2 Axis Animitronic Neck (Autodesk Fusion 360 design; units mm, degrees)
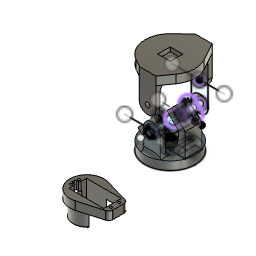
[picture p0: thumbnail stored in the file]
sketch "Sketch1" plane through (0, 0, 0) normal (0, 0, 1) x axis (1, 0, 0)
  line L1 (-39.2157, 5) -> (0, 5)
  line L2 (-39.2157, -5) -> (0, -5)
  line L3 (-14.1421, 5) -> (-14.1421, -5)
  line L4 (33.8579, 5) -> (33.8579, -5)
  line L5 (30.8579, -10.5) -> (0, -10.5)
  line L6 (30.8579, 10.5) -> (0, 10.5)
  line L7 (33.8579, 0) -> (-14.1421, 0)
  line L8 (30.8579, -10.5) -> (30.8579, 0)
  line L9 (30.8579, 10.5) -> (30.8579, 0)
  line L10 (-11.1421, 10.5) -> (-11.1421, 0)
  line L11 (-11.1421, -10.5) -> (-11.1421, 0)
  line L12 (37.8579, 10.5) -> (37.8579, 0)
  line L13 (37.8579, -10.5) -> (37.8579, 0)
  line L14 (5.6339, 19.7106) -> (37.8579, 10.5)
  line L15 (5.6339, -19.7106) -> (37.8579, -10.5)
  line L16 (-11.1421, 10.5) -> (0, 10.5)
  line L17 (-11.1421, -10.5) -> (0, -10.5)
  circle C1 centre (0, 0) radius 15
  circle C2 centre (-14.1421, -5) radius 1.5
  circle C3 centre (-14.1421, 5) radius 1.5
  circle C4 centre (33.8579, 5) radius 1.5
  circle C5 centre (33.8579, -5) radius 1.5
  arc A1 centre (0, 0) radius 20.5 clockwise from (5.6339, -19.7106) to (5.6339, 19.7106)
  arc A2 centre (0, 0) radius 16.625 clockwise from (12.8896, -10.5) to (12.8896, 10.5)
  point P1 (0, 0)
  point P2 (0, 0)
  point P8 (-14.1421, -5)
  point P9 (-14.1421, 5)
  point P10 (-14.1421, -5)
  point P11 (-14.1421, 5)
  point P13 (33.8579, 5)
  point P14 (33.8579, 5)
  point P12 (33.8579, -5)
  point P15 (33.8579, -5)
  point P18 (-14.1421, 0)
  point P19 (33.8579, 0)
  point P32 (12.8896, 10.5)
  point P33 (12.8896, -10.5)
  coincident P1 P2
  coincident C1 P8
  coincident L2 P8
  coincident C1 P9
  coincident L1 P9
  coincident P8 P10
  coincident P9 P11
  coincident P13 P14
  coincident P12 P15
  midpoint L3 P18
  midpoint L4 P19
  perpendicular L4 L7
  coincident L6 P32
  coincident L5 P33
  dimension "d1" diameter A2 = 33.25
  dimension "d3" diameter C1 = 30
  dimension "d6" diameter C2 = 3
  dimension "d7" diameter C3 = 3
  dimension "d8" = 48
  dimension "d9" diameter C4 = 3
  dimension "d10" diameter C5 = 3
extrude "Extrude1" new body sketch "Sketch1" profile of A2 A1 C2 C3 C4 C5 L17 L5 L16 L6 L9 L8 L11 L10 L13 L12 L14 L15 along normal blind 10
extrude "Extrude2" add sketch "Sketch1" profile of A2 C2 C3 L17 L5 L16 L6 L11 L10 against normal blind 20
sketch "Sketch2" plane through (0, 0, -20) normal (0, 0, -1) x axis (1, 0, 0)
  line L1 (-11.1421, -10.5) -> (12.8896, -10.5)
  line L2 (-11.1421, 10.5) -> (-11.1421, -10.5)
  line L3 (12.8896, 10.5) -> (-11.1421, 10.5)
  line L4 (-19.0195, 0) -> (-11.1421, 0)
  line L5 (-19.0195, -5) -> (-19.0195, 0)
  line L6 (-11.1421, -5) -> (-19.0195, -5)
  line L7 (-19.0195, 5) -> (-19.0195, 0)
  line L8 (-11.1421, 5) -> (-19.0195, 5)
  circle C1 centre (-14.1421, 5) radius 1.5
  circle C2 centre (-14.1421, -5) radius 1.5
  arc A1 centre (0, 0) radius 16.625 clockwise from (12.8896, -10.5) to (12.8896, 10.5)
  point P9 (-11.1421, 0)
  point P12 (-11.1421, -5)
  point P14 (-11.1421, 5)
  point P10 (-19.0195, 0)
  point P11 (-19.0195, -5)
  point P13 (-19.0195, 5)
  midpoint L2 P9
  perpendicular L2 L4
  perpendicular L4 L5
  coincident L2 P12
  perpendicular L2 L6
  perpendicular L4 L7
  coincident L2 P14
  perpendicular L2 L8
  dimension "d20" distance P10 P11 = 5
  dimension "d21" distance P10 P13 = 5
extrude "Extrude3" add sketch "Sketch1" profile of C2 C3 against normal blind 20
extrude "Extrude4" cut sketch "Sketch2" profile of C1 C2 L2 A1 L4 L6 L8 against normal blind 20
sketch "Sketch3" plane through (0, 0, 10) normal (0, 0, 1) x axis (-1, 0, 0)
  line L1 (-30.8579, 10.5) -> (-30.8579, -10.5)
  line L2 (11.1421, 10.5) -> (-30.8579, 10.5)
  line L3 (11.1421, -10.5) -> (11.1421, 10.5)
  line L4 (-30.8579, -10.5) -> (11.1421, -10.5)
  line L5 (-37.8579, -10.5) -> (-37.8579, 10.5)
  line L6 (-5.6339, -19.7106) -> (-37.8579, -10.5)
  line L7 (-37.8579, 10.5) -> (-5.6339, 19.7106)
  line L8 (16.1421, 0) -> (11.1421, 0)
  line L9 (16.1421, -2.5) -> (16.1421, 0)
  line L10 (11.1421, -2.5) -> (16.1421, -2.5)
  line L11 (16.1421, 2.5) -> (16.1421, 0)
  line L12 (11.1421, 2.5) -> (16.1421, 2.5)
  circle C1 centre (14.1421, -5) radius 1.5
  circle C2 centre (14.1421, 5) radius 1.5
  circle C3 centre (-33.8579, -5) radius 1.5
  circle C4 centre (-33.8579, 5) radius 1.5
  arc A1 centre (0, 0) radius 20.5 clockwise from (-5.6339, 19.7106) to (-5.6339, -19.7106)
  point P15 (11.1421, 0)
  point P18 (11.1421, -2.5)
  point P20 (11.1421, 2.5)
  point P16 (16.1421, 0)
  point P17 (16.1421, -2.5)
  point P19 (16.1421, 2.5)
  midpoint L3 P15
  perpendicular L3 L8
  perpendicular L8 L9
  coincident L3 P18
  perpendicular L3 L10
  perpendicular L8 L11
  coincident L3 P20
  perpendicular L3 L12
  dimension "d26" distance P15 P16 = 5
  dimension "d27" distance P16 P17 = 2.5
  dimension "d28" distance P16 P19 = 2.5
extrude "Extrude5" cut sketch "Sketch3" profile of L3 L8 L9 L10 L11 L12 against normal blind 21
fillet "Fillet1" radius 1.5
fillet "Fillet2" radius 1.5
fillet "Fillet3" radius 5
fillet "Fillet4" radius 2
move "Move1"
sketch "Sketch1" plane through (0, 0, 0) normal (0, 0, 1) x axis (1, 0, 0)
  line L1 (0, 24) -> (0, 0)
  line L2 (4, 24) -> (4, 12.2838)
  line L3 (-4, 24) -> (-4, 12.2838)
  circle C1 centre (0, 0) radius 30
  arc A1 centre (0, 24) radius 4 clockwise from (-4, 24) to (4, 24)
  arc A2 centre (0, 0) radius 7.625 clockwise from (6.4033, 4.1398) to (-6.4033, 4.1398)
  circle C2 centre (0, 24) radius 1.5
  arc A3 centre (-19, 12.2838) radius 15 clockwise from (-4, 12.2838) to (-6.4033, 4.1398)
  arc A4 centre (19, 12.2838) radius 15 clockwise from (6.4033, 4.1398) to (4, 12.2838)
  point P1 (0, 0)
  point P2 (0, 0)
  point P4 (0, 0)
  point P5 (0, 24)
  point P6 (0, 24)
  coincident P1 P2
  concentric C1 A2
  coincident P2 P4
  vertical L1
  coincident P5 P6
  concentric A1 C2
  tangent L3 A3
  tangent A2 A3
  tangent L2 A4
  tangent A2 A4
  dimension "d39" diameter C1 = 60
  dimension "d40" diameter A2 = 15.25
  dimension "d41" distance P4 P5 = 24
  dimension "d42" diameter A1 = 8
  dimension "d45" diameter C2 = 3
  dimension "d46" radius A3 = 15
  dimension "d47" radius A4 = 15
extrude "Extrude1" new body sketch "Sketch1" profile of C1 A2 A1 L2 L3 C2 A3 A4 along normal blind 10
extrude "Extrude2" cut sketch "Sketch1" profile of A2 A1 L2 L3 C2 A3 A4 along normal blind 7
sketch "Sketch2" plane through (0, 0, 10) normal (0, 0, 1) x axis (-1, 0, 0)
  line L1 (54.6614, 0) -> (0, 0)
  line L2 (-20, 0) -> (0, 0)
  line L3 (-20, 10) -> (-20, 0)
  line L4 (-28, 10) -> (-20, 10)
  line L5 (-28, -10) -> (-28, 10)
  line L6 (-20, -10) -> (-28, -10)
  line L7 (-20, 0) -> (-20, -10)
  circle C1 centre (0, 0) radius 30
  point P2 (0, 0)
  point P3 (0, 0)
  point P5 (-20, 0)
  point P6 (-20, 10)
  point P7 (-28, 10)
  point P8 (-28, -10)
  coincident P2 P3
  horizontal L1
  parallel L1 L2
  perpendicular L1 L3
  perpendicular L3 L4
  perpendicular L1 L5
  perpendicular L5 L6
  perpendicular L2 L7
  dimension "d52" distance P3 P5 = 20
  dimension "d53" distance P5 P6 = 10
  dimension "d54" distance P6 P7 = 8
  dimension "d55" distance P7 P8 = 20
extrude "Extrude3" add sketch "Sketch2" profile of L3 L4 L5 L6 L7 along normal blind 25
sketch "Sketch3" plane through (0, 10, 0) normal (0, 1, 0) x axis (-1, 0, 0)
  line L1 (-20, 10) -> (-28, 10)
  line L2 (-20, 35) -> (-20, 10)
  line L3 (-28, 35) -> (-20, 35)
  line L4 (-28, 10) -> (-28, 35)
  line L5 (-5.8579, 49.1421) -> (-20, 35)
  line L6 (25, 35) -> (-20, 35)
  line L7 (-11.5147, 54.799) -> (-28, 38.3137)
  line L8 (-28, 38.3137) -> (-28, 35)
  line L9 (-25.6569, 40.6569) -> (-20, 35)
  line L10 (-11.5147, 54.799) -> (-5.8579, 49.1421)
  point P4 (-20, 35)
  point P6 (-20, 35)
  point P5 (-28, 35)
  point P8 (-28, 35)
  point P10 (-20, 35)
  point P11 (-25.6569, 40.6569)
  horizontal L6
  coincident P4 P6
  coincident P5 P8
  perpendicular L3 L8
  coincident P4 P10
  perpendicular L7 L9
  coincident L7 P11
  dimension "d59" angle L5 L6 = 45
  dimension "d61" = 20
extrude "Extrude4" add sketch "Sketch3" profile of L3 L5 L8 L7 L9 L10 against normal blind 20
sketch "Sketch4" plane through (0, 10, 0) normal (0, 1, 0) x axis (-1, 0, 0)
  line L1 (-20, 10) -> (-28, 10)
  line L2 (-20, 35) -> (-20, 10)
  line L3 (-5.8579, 49.1421) -> (-20, 35)
  line L4 (-11.5147, 54.799) -> (-5.8579, 49.1421)
  line L5 (-28, 38.3137) -> (-11.5147, 54.799)
  line L6 (-28, 10) -> (-28, 38.3137)
  line L7 (-11.5147, 49.1421) -> (-8.6863, 51.9706)
  line L8 (-18.5858, 42.0711) -> (-11.5147, 49.1421)
  line L9 (23.1335, 14.4939) -> (-11.5147, 49.1421)
  line L10 (16.0624, 7.4228) -> (-18.5858, 42.0711)
  line L11 (21.4524, -6.4524) -> (-20, 35)
  line L12 (-5.8579, 49.1421) -> (-20, 35)
  line L13 (23.1335, 20.1508) -> (8.9914, 6.0086)
  line L14 (14.6482, 0.3518) -> (8.9914, 6.0086)
  line L15 (28.1635, 13.867) -> (14.6482, 0.3518)
  line L16 (25.9619, 11.6655) -> (23.1335, 14.4939)
  circle C1 centre (-11.5147, 49.1421) radius 1.5
  circle C2 centre (-18.5858, 42.0711) radius 1.5
  circle C3 centre (23.1335, 14.4939) radius 1.5
  circle C4 centre (16.0624, 7.4228) radius 1.5
  point P8 (-8.6863, 51.9706)
  point P9 (-11.5147, 49.1421)
  point P11 (-11.5147, 49.1421)
  point P10 (-18.5858, 42.0711)
  point P12 (-18.5858, 42.0711)
  point P13 (23.1335, 14.4939)
  point P15 (23.1335, 14.4939)
  point P14 (16.0624, 7.4228)
  point P16 (16.0624, 7.4228)
  point P4 (-20, 35)
  point P17 (-20, 35)
  point P5 (-5.8579, 49.1421)
  point P19 (-5.8579, 49.1421)
  point P22 (14.6482, 0.3518)
  point P24 (23.1335, 14.4939)
  point P25 (25.9619, 11.6655)
  point P20 (8.9914, 6.0086)
  midpoint L4 P8
  perpendicular L4 L7
  perpendicular L4 L8
  coincident P9 P11
  coincident P10 P12
  perpendicular L3 L9
  perpendicular L8 L10
  coincident P13 P15
  coincident P14 P16
  coincident P4 P17
  perpendicular L3 L11
  coincident P5 P19
  coincident L11 P22
  perpendicular L13 L14
  perpendicular L11 L15
  coincident P15 P24
  coincident L15 P25
  perpendicular L15 L16
  dimension "d64" distance P8 P9 = 4
  dimension "d65" distance P9 P10 = 10
  dimension "d66" diameter C1 = 3
  dimension "d67" diameter C2 = 3
  dimension "d68" distance P9 P13 = 49
  dimension "d69" distance P10 P14 = 49
  dimension "d70" diameter C3 = 3
  dimension "d71" diameter C4 = 3
  dimension "d72" = 41
  dimension "d75" distance P20 P22 = 8
extrude "Extrude5" cut sketch "Sketch4" profile of L3 L9 L10 L11 L12 L13 against normal blind 30
extrude "Extrude6" cut sketch "Sketch4" profile of L3 L9 L10 C3 C4 L11 L12 L13 L14 L15 L16 along normal blind 28
sketch "Sketch5" plane through (-7.5, 0, 7.5) normal (-0.7071, 0, 0.7071) x axis (0, -1, 0)
  line L1 (-29.5804, 3.5355) -> (20, 3.5355)
  line L2 (-10, -10.1091) -> (-26.1807, -10.1091)
  line L3 (-10, -2.1091) -> (-10, -10.1091)
  line L4 (20, -2.1091) -> (-10, -2.1091)
  line L5 (20, 3.5355) -> (20, -2.1091)
  line L6 (-10, -10.1091) -> (-10, -2.1091)
  line L7 (10, -2.1091) -> (-10, -2.1091)
  line L8 (10, -10.1091) -> (-10, -10.1091)
  line L9 (10, -10.1091) -> (10, -2.1091)
  closed curve K1 centre (0, 10.6066)
  point P7 (-10, -2.1091)
  point P9 (-10, -2.1091)
  point P6 (-10, -10.1091)
  point P10 (-10, -10.1091)
  point P11 (10, -2.1091)
  point P12 (10, -10.1091)
  coincident P7 P9
  coincident P6 P10
  perpendicular L3 L7
  perpendicular L3 L8
  dimension "d78" distance P9 P11 = 20
  dimension "d79" distance P10 P12 = 20
extrude "Extrude7" add sketch "Sketch5" profile of L3 L4 L6 L7 L8 L9 along normal blind 20
extrude "Extrude8" cut sketch "Sketch4" profile of L7 L8 C1 C2 L9 L10 C3 C4 L16 against normal blind 15
extrude "Extrude9" cut sketch "Sketch1" profile of C2 along normal blind 10
sketch "Sketch6" plane through (0, 10, 0) normal (0, 1, 0) x axis (-1, 0, 0)
  line L1 (-13.2168, 43.7732) -> (-16.8837, 47.44)
  line L2 (-18.5858, 42.0711) -> (-11.5147, 49.1421)
  line L3 (-4.4437, 35) -> (-15.0503, 45.6066)
  point P6 (-15.0503, 45.6066)
  point P7 (-4.4437, 35)
  perpendicular L1 L2
  midpoint L2 P6
  perpendicular L2 L3
  dimension "d86" distance P6 P7 = 15
sketch "Sketch7" plane through (0, 0, 0) normal (0, 1, 0) x axis (1, 0, 0)
work_plane "WorkPlane1"
sketch "Sketch8" plane through (-15.2782, 0, 15.2782) normal (-0.7071, 0, 0.7071) x axis (0, -1, 0)
  line L1 (40, 27.8909) -> (-10, 27.8909)
  line L2 (-31, 27.8909) -> (-10, 27.8909)
  point P2 (-10, 27.8909)
  point P3 (-10, 27.8909)
  point P4 (40, 27.8909)
  point P5 (-31, 27.8909)
  coincident P2 P3
  dimension "d88" distance P3 P4 = 50
  dimension "d89" distance P3 P5 = 21
sketch "Sketch9" plane through (0, 0, 10) normal (0, 0, 1) x axis (-1, 0, 0)
  line L1 (-27.1003, 20) -> (5, 20)
  line L2 (-4.4437, 40) -> (-4.4437, -10)
  line L3 (-14.4437, 20) -> (-4.4437, 20)
  line L4 (-14.4437, 28.5869) -> (-14.4437, 20)
  line L5 (5.5563, 20) -> (-4.4437, 20)
  line L6 (5.5563, 30.6716) -> (5.5563, 20)
  line L7 (30.4984, 20) -> (5.5563, 20)
  line L8 (-14.4437, 26.2941) -> (-14.4437, 20)
  line L9 (5.5563, 26.2941) -> (-14.4437, 26.2941)
  circle C1 centre (0, 0) radius 30
  point P2 (5, 20)
  point P4 (5, 20)
  point P7 (-4.4437, 20)
  point P1 (0, 0)
  point P14 (0, 0)
  point P15 (-14.4437, 26.2941)
  point P16 (5.5563, 26.2941)
  point P8 (-14.4437, 20)
  point P10 (5.5563, 20)
  horizontal L1
  coincident P2 P4
  coincident L1 P7
  coincident L2 P7
  perpendicular L2 L3
  perpendicular L1 L4
  perpendicular L2 L5
  perpendicular L5 L6
  perpendicular L6 L7
  coincident P1 P14
  coincident C1 P15
  coincident L4 P15
  coincident L6 P16
  perpendicular L6 L9
  dimension "d90" distance P7 P8 = 10
  dimension "d91" distance P7 P10 = 10
  dimension "d92" diameter C1 = 60
extrude "Extrude10" add sketch "Sketch9" profile of L1 L2 L3 L4 L5 L6 L8 L9 along normal blind 35
sketch "Sketch10" plane through (0, -26.2941, 0) normal (0, -1, 0) x axis (1, 0, 0)
  line L1 (14.4437, 10) -> (-5.5563, 10)
  line L2 (14.4437, 45) -> (14.4437, 10)
  line L3 (-5.5563, 45) -> (14.4437, 45)
  line L4 (-5.5563, 10) -> (-5.5563, 45)
  circle C1 centre (4.4437, 35) radius 2.5
  point P6 (4.4437, 35)
  point P7 (4.4437, 35)
  coincident P6 P7
  dimension "d95" diameter C1 = 5
extrude "Extrude11" add sketch "Sketch10" profile of C1 along normal blind 5
fillet "Fillet1" radius 2
fillet "Fillet2" radius 10
fillet "Fillet3" radius 10
work_plane "WorkPlane1" sketch "Sketch2" AlongDistance 50
sketch "Sketch1" plane through (0, 0, 60) normal (0, 0, 1) x axis (1, 0, 0)
  line L1 (0, -41.1075) -> (0, 0)
  line L2 (4.4437, -40) -> (4.4437, 10)
  line L3 (4.4437, 31) -> (4.4437, 10)
  line L4 (-19.2926, 31) -> (4.4437, 31)
  circle C1 centre (0, 0) radius 30
  point P2 (0, 0)
  point P3 (0, 0)
  point P4 (0, 0)
  point P8 (4.4437, 31)
  point P9 (4.4437, 31)
  coincident P2 P3
  coincident P2 P4
  vertical L1
  coincident P8 P9
  perpendicular L3 L4
  dimension "d105" diameter C1 = 60
work_plane "WorkPlane2"
sketch "Sketch2" plane through (0, 31, 0) normal (0, 1, 0) x axis (1, 0, 0)
  line L1 (33.9028, -60) -> (4.4437, -60)
  line L2 (14.4437, -60) -> (14.4437, -35)
  line L3 (-28.6272, -60) -> (4.4437, -60)
  line L4 (-5.5563, -60) -> (-5.5563, -35)
  circle C1 centre (4.4437, -35) radius 4
  circle C2 centre (4.4437, -35) radius 10
  point P2 (4.4437, -35)
  point P3 (4.4437, -35)
  point P4 (4.4437, -35)
  point P5 (4.4437, -60)
  point P7 (4.4437, -60)
  point P8 (14.4437, -35)
  point P9 (14.4437, -60)
  point P11 (-5.5563, -35)
  point P12 (-5.5563, -60)
  coincident P2 P3
  coincident P3 P4
  horizontal L1
  coincident P5 P7
  coincident C2 P8
  coincident L1 P9
  perpendicular L1 L2
  tangent C2 L2
  parallel L1 L3
  coincident C2 P11
  coincident L3 P12
  perpendicular L3 L4
  tangent C2 L4
  dimension "d106" diameter C1 = 8
  dimension "d107" diameter C2 = 20
extrude "Extrude1" new body sketch "Sketch2" along normal blind 5
extrude "Extrude2" add sketch "Sketch2" profile of C1 against normal blind 1.5
sketch "Sketch3" plane through (0, 0, 60) normal (0, 0, 1) x axis (1, 0, 0)
  line L1 (-20.5856, 21.8228) -> (-5.5563, 36)
  line L2 (26.2893, 14.4524) -> (14.4437, 36)
  line L3 (14.4437, 36) -> (-5.5563, 36)
  circle C1 centre (0, 0) radius 30
  point P2 (-5.5563, 36)
  point P3 (-5.5563, 36)
  point P5 (-20.5856, 21.8228)
  point P6 (14.4437, 36)
  point P7 (14.4437, 36)
  point P8 (26.2893, 14.4524)
  point P9 (-5.5563, 36)
  point P10 (14.4437, 36)
  coincident P2 P3
  tangent L1 C1
  coincident C1 P5
  coincident P6 P7
  tangent C1 L2
  coincident C1 P8
  coincident P3 P9
  coincident P7 P10
move "Move1"
extrude "Extrude3" new body sketch "Sketch2" along normal blind 5
extrude "Extrude4" add sketch "Sketch2" profile of C1 against normal blind 1.5
extrude "Extrude5" cut of existing geometry blind -1.5
sketch "Sketch4" plane through (0, -31.5, 0) normal (0, -1, 0) x axis (1, 0, 0)
  line L1 (14.4437, 60) -> (14.4437, 35)
  line L2 (-5.5563, 60) -> (14.4437, 60)
  line L3 (-5.5563, 35) -> (-5.5563, 60)
  arc A1 centre (4.4437, 35) radius 10 clockwise from (14.4437, 35) to (-5.5563, 35)
  circle C1 centre (4.4437, 35) radius 2.875
  concentric A1 C1
  dimension "d118" diameter C1 = 5.75
extrude "Extrude12" cut sketch "Sketch4" profile of C1 against normal blind 5
sketch "Sketch5" plane through (0, 0, 60) normal (0, 0, 1) x axis (1, 0, 0)
  line L1 (-15.1365, -25.9015) -> (-5.5563, -31.5)
  line L2 (24.4747, -17.3491) -> (14.4437, -31.5)
  line L3 (14.4437, -31.5) -> (-5.5563, -31.5)
  circle C1 centre (0, 0) radius 30
  point P2 (-5.5563, -31.5)
  point P3 (-5.5563, -31.5)
  point P5 (-15.1365, -25.9015)
  point P6 (14.4437, -31.5)
  point P7 (14.4437, -31.5)
  point P8 (24.4747, -17.3491)
  coincident P2 P3
  tangent L1 C1
  coincident C1 P5
  coincident P6 P7
  tangent C1 L2
  coincident C1 P8
extrude "Extrude7" add sketch "Sketch3" + "Sketch5" + "Sketch1" profile of S3:C1 S3:L2 S3:L3 S1:L1 S1:C1 S1:L2 S1:L3 S2:L1 S2:C1 S2:L2 S2:L3 blind 10
sketch "Sketch6" plane through (0, 29.5, 0) normal (0, -1, 0) x axis (1, 0, 0)
  circle C1 centre (4.4437, 35) radius 4
  circle C2 centre (4.4437, 35) radius 1.75
  concentric C1 C2
  dimension "d125" diameter C2 = 3.5
extrude "Extrude8" cut sketch "Sketch6" profile of C2 against normal blind 23
move "Move2"
extrude "Extrude13" add of existing geometry blind 5
fillet "Fillet4" radius 2
fillet "Fillet1" radius 10
fillet "Fillet2" radius 10
fillet "Fillet5" radius 20
fillet "Fillet6" radius 5
fillet "Fillet7" radius 5
sketch "Sketch7" plane through (0, 0, 100) normal (0, 0, 1) x axis (-1, 0, 0)
  line L1 (20.5856, -21.8228) -> (5.5563, -36)
  line L2 (5.5563, 31.5) -> (15.1365, 25.9015)
  line L3 (-14.4437, 31.5) -> (5.5563, 31.5)
  line L4 (-24.4747, 17.3491) -> (-14.4437, 31.5)
  line L5 (-14.4437, -36) -> (-26.2893, -14.4524)
  line L6 (5.5563, -36) -> (-14.4437, -36)
  line L7 (-7.5, 7.5) -> (7.5, 7.5)
  line L8 (-7.5, -7.5) -> (-7.5, 7.5)
  line L9 (7.5, -7.5) -> (-7.5, -7.5)
  line L10 (7.5, 7.5) -> (7.5, -7.5)
  line L11 (-7.5, -7.5) -> (7.5, 7.5)
  line L12 (7.5, -7.5) -> (-7.5, 7.5)
  arc A1 centre (0, 0) radius 30 clockwise from (15.1365, 25.9015) to (20.5856, -21.8228)
  arc A2 centre (0, 0) radius 30 clockwise from (-26.2893, -14.4524) to (-24.4747, 17.3491)
  point P15 (0, 0)
  point P1 (0, 0)
  point P13 (-7.5, -7.5)
  point P14 (7.5, -7.5)
  point P12 (-7.5, 7.5)
  horizontal L7
  perpendicular L7 L8
  parallel L7 L9
  parallel L8 L10
  coincident L11 P15
  coincident L12 P15
  coincident P1 P15
  dimension "d142" distance P13 P14 = 15
  dimension "d143" distance P12 P13 = 15
extrude "Extrude9" cut sketch "Sketch7" profile of L7 L8 L9 L10 against normal blind 5
fillet "Fillet3" radius 1
sketch "Sketch8" plane through (0, 31, 0) normal (0, -1, 0) x axis (1, 0, 0)
  line L1 (-5.5563, 80) -> (14.4437, 80)
  line L2 (-5.5563, 65) -> (-5.5563, 80)
  line L3 (14.4437, 80) -> (14.4437, 65)
  line L4 (4.4437, 95) -> (4.4437, 65)
  line L5 (8.2437, 95) -> (8.2437, 65)
  line L6 (0.6437, 95) -> (0.6437, 65)
  line L7 (8.2437, 95) -> (0.6437, 95)
  line L8 (8.2437, 73.7659) -> (0.6437, 73.7659)
  arc A1 centre (4.4437, 65) radius 10 clockwise from (14.4437, 65) to (-5.5563, 65)
  circle C1 centre (4.4437, 65) radius 4
  point P6 (4.4437, 65)
  point P7 (4.4437, 65)
  point P13 (0.6437, 73.7659)
  point P14 (8.2437, 73.7659)
  point P8 (4.4437, 95)
  perpendicular L1 L4
  coincident P6 P7
  perpendicular L5 L7
  coincident L6 P13
  coincident L5 P14
  perpendicular L5 L8
  dimension "d148" distance P7 P8 = 30
  dimension "d149" = 3.8
  dimension "d150" = -3.8
extrude "Extrude10" cut sketch "Sketch8" profile of L1 L4 L5 L6 L7 L8 along normal blind 10
fillet "Fillet4" radius 2
fillet "Fillet5" radius 2
fillet "Fillet6" radius 2
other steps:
extrude "Extrude6" cut sketch "Sketch4" profile of C1 against normal blind 5
create_component "CreateComponent1"
create_component "CreateComponent2"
